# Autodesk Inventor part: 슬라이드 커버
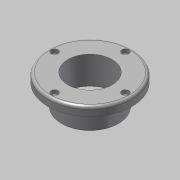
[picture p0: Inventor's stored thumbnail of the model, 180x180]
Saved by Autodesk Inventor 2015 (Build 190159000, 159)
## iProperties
Created: 2015-10
Part Number: 슬라이드 커버
Document SubType Name: Modeling
Designer: mdu
Density: 7.86 g/cm^3
Material: 강철, 연강
Mass: 633.012 g
Surface Area: 239.629 cm^2
Volume: 80.5358 cm^3
Appearance: 강철
Author: mdu
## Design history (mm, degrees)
sketch "스케치1"
  geometry: C1 r 47.5 at (0, 0); C2 r 32.5 at (0, 0); 1 further point
  constraints: 2 centre point, 2 coincident
  dimensions: "d33" = 95 diameter of C1; "d35" = 65 diameter of C2
extrude "돌출1" new body sketch "스케치1" distance "d0" = 10; taper "d1" = 0 deg
extrude "돌출2" join sketch "스케치1" distance "d2" = 25; taper "d3" = 0 deg
hole "구멍1" diameter "d6" = 50; stored, may be unused: countersink angle "d10" = 90 deg, drill point angle "d12" = 118 deg; dims "d4" = 10, "d5" = 10, "d7" = 6, "d8" = 4, "d9" = 2, "d11" = 8
sketch "스케치2" dims "d36" = 80
  geometry: 4 further points
  constraints: 2 coincident, 2 vertical alignment, 2 other
hole "구멍2" sketch "스케치2" at (0, 40) diameter "d13" = 4.5; stored, may be unused: countersink angle "d17" = 90 deg, drill point angle "d19" = 118 deg; dims "d14" = 6, "d15" = 8, "d16" = 4.4, "d18" = 8
fillet "모깎기1" dims "d23" = 3
chamfer "모따기1" distance "d24" = 1; stored, may be unused: second distance "d25" = 2, angle "d26" = 45 deg
sketch "스케치3"
  geometry: C1 r 25 at (0, 0); C2 r 30 at (0, 0); C3 r 26 at (0, 0) reference; 1 further point
  constraints: 2 centre point, 2 coincident
  dimensions: "d27" = 60 diameter of C2
extrude "돌출3" cut sketch "스케치3" distance "d28" = 3; taper "d29" = 0 deg
chamfer "모따기2" distance "d30" = 1; stored, may be unused: second distance "d31" = 2, angle "d32" = 45 deg
node "솔리드1"
pattern_circular "원형 패턴1" dims angle "d21" = 360 deg
